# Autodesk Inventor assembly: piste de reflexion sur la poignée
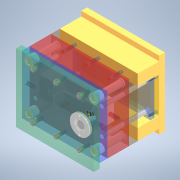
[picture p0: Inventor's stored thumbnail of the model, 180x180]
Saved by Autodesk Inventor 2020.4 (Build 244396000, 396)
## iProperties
Created: 2021-10
Part Number: piste de reflexion sur la poignée
Document SubType Name: Assembly
Designer: mel
Author: mel
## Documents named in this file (6)
- D:\travail\année 2020-2021\itec\prépa injection plastique eduscol\dossier de travail\Ensemble des pièces de l'activité\Conception de moule2\piste de reflexion sur la poignée.iam
- D:\travail\année 2020-2021\itec\prépa injection plastique eduscol\dossier de travail\Ensemble des pièces de l'activité\Conception de moule2\piste de reflexion sur la poignée_exemple de poignée_LY.iam
- D:\travail\année 2020-2021\itec\prépa injection plastique eduscol\dossier de travail\Ensemble des pièces de l'activité\Conception de moule2\piste de reflexion sur la poignée_RG.ipt
- D:\travail\année 2020-2021\itec\prépa injection plastique eduscol\dossier de travail\Ensemble des pièces de l'activité\Conception de moule2\Mo\FUTABA_SA-S 1\piste de reflexion sur la poignée_MB.iam
- D:\travail\année 2020-2021\itec\prépa injection plastique eduscol\dossier de travail\Ensemble des pièces de l'activité\Conception de moule2\Buse d'injection\HASCO_Z51\piste de reflexion sur la poignée_Z51-18x56-3,5.ipt
- D:\travail\année 2020-2021\itec\prépa injection plastique eduscol\dossier de travail\Ensemble des pièces de l'activité\Conception de moule2\Bague de centrage\LKM_LR\piste de reflexion sur la poignée_LR-100-36.ipt
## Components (5 placed, 5 different names)
1. piste de reflexion sur la poignée_exemple de poignée_LY:1 [sub-assembly] — Affleurement:1, Affleurement:2, Affleurement:3, Affleurement:10, Affleurement:11
2. piste de reflexion sur la poignée_RG:1 — Affleurement:4, Affleurement:5, Affleurement:6, Affleurement:8, Placage:3
3. piste de reflexion sur la poignée_MB:1 [sub-assembly] — Placage:1, Angle:1, Placage:2, Placage:4, Affleurement:11
4. piste de reflexion sur la poignée_Z51-18x56-3,5:1 — Placage:2, Placage:3, Placage:5
5. piste de reflexion sur la poignée_LR-100-36:1 — Placage:4, Placage:5
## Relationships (15: Flush 9, Mate 5, Angle 1)
- Affleurement:1 [Flush]: piste de reflexion sur la poignée_exemple de poignée_LY:1
- Affleurement:2 [Flush]: piste de reflexion sur la poignée_exemple de poignée_LY:1
- Affleurement:3 [Flush]: piste de reflexion sur la poignée_exemple de poignée_LY:1
- Affleurement:4 [Flush]: piste de reflexion sur la poignée_RG:1
- Affleurement:5 [Flush]: piste de reflexion sur la poignée_RG:1
- Affleurement:6 [Flush]: piste de reflexion sur la poignée_RG:1
- Affleurement:8 [Flush]: piste de reflexion sur la poignée_RG:1
- Placage:1 [Mate]: piste de reflexion sur la poignée_MB:1
- Angle:1: piste de reflexion sur la poignée_MB:1
- Placage:2 [Mate]: piste de reflexion sur la poignée_MB:1 ↔ piste de reflexion sur la poignée_Z51-18x56-3,5:1
- Placage:3 [Mate]: piste de reflexion sur la poignée_RG:1 ↔ piste de reflexion sur la poignée_Z51-18x56-3,5:1
- Placage:4 [Mate]: piste de reflexion sur la poignée_MB:1 ↔ piste de reflexion sur la poignée_LR-100-36:1
- Placage:5 [Mate]: piste de reflexion sur la poignée_Z51-18x56-3,5:1 ↔ piste de reflexion sur la poignée_LR-100-36:1
- Affleurement:10 [Flush]: piste de reflexion sur la poignée_exemple de poignée_LY:1
- Affleurement:11 [Flush]: piste de reflexion sur la poignée_exemple de poignée_LY:1 ↔ piste de reflexion sur la poignée_MB:1
